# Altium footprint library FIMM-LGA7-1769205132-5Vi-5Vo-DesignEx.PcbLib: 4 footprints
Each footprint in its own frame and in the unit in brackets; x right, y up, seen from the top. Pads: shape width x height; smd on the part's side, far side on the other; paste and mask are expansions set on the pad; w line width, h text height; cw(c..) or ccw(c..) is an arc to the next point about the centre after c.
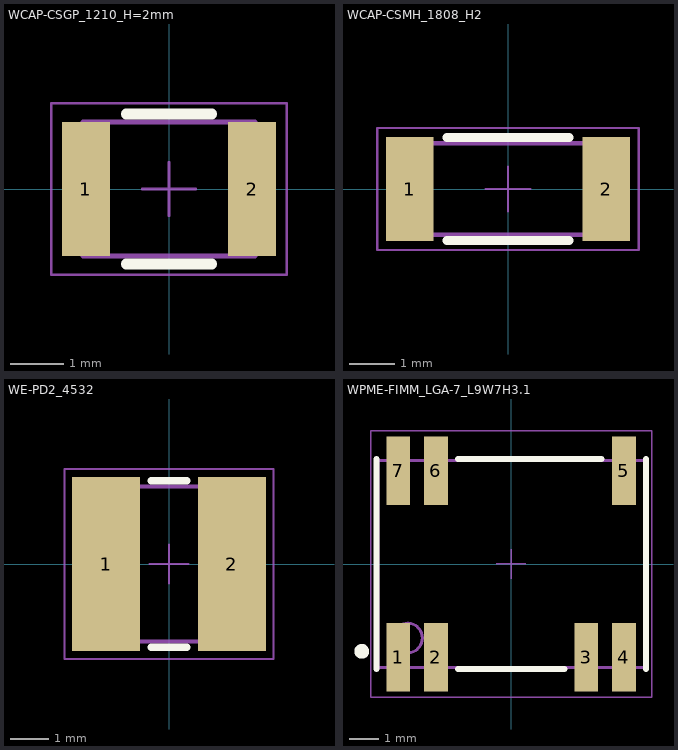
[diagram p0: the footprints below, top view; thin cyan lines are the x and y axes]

## WCAP-CSGP_1210_H=2mm [mm] "Ceramic Capacitors, body 3.2x2.5mm"
height 2.2
pads (2):
  rect 0.9x2.5 smd: 1(-1.55,0) 2(1.55,0)
Top Overlay:
  lines w0.2: -0.8,-1.4 0.8,-1.4 ; -0.8,1.4 0.8,1.4
Top Assembly:
  lines w0.1: -1.6,-1.25 1.6,-1.25 1.6,1.25 -1.6,1.25 -1.6,-1.25
  text ".Designator" at -1.4,-0.6 h1.2
Top 3D Body:
  lines w0.1: -1.6,-1.25 1.6,-1.25 1.6,1.25 -1.6,1.25 -1.6,-1.25
Top Courtyard:
  lines w0.05: -0.5,0 0.5,0 ; 0,-0.5 0,0.5 ; -2.2,-1.6 -2.2,1.6 2.2,1.6 2.2,-1.6 -2.2,-1.6
3D body "3.2x2.5x2x0.75.stp": height 2, standoff 0, extent -1.6,-1.25 1.6,1.25

## WCAP-CSMH_1808_H2 [mm] "Ceramic Capacitors, body 4.5x2.03mm"
height 2
pads (2):
  rect 1.05x2.3 smd: 1(-2.175,0) 2(2.175,0)
Top Overlay:
  lines w0.2: -1.35,-1.14 1.35,-1.14 ; -1.35,1.14 1.35,1.14
Top Assembly:
  lines w0.1: -2.25,-1.015 -2.25,1.015 2.25,1.015 2.25,-1.015 -2.25,-1.015
Top 3D Body:
  lines w0.1: -2.25,-1.015 2.25,-1.015 2.25,1.015 -2.25,1.015 -2.25,-1.015
Top Courtyard:
  lines w0.05: -0.5,0 0.5,0 ; 0,-0.5 0,0.5 ; -2.9,-1.35 -2.9,1.35 2.9,1.35 2.9,-1.35 -2.9,-1.35
3D body "4.5x2.03x2x0.5.stp": height 2, standoff 0, extent -2.25,-1.015 2.25,1.015

## WE-PD2_4532 [mm] "SMD Power Inductor, 2-Leads, body 4x4.5mm"
height 3.2
pads (2):
  rect 1.75x4.5 smd: 1(-1.625,0) 2(1.625,0)
Top Overlay:
  lines w0.2: -0.45,-2.15 0.45,-2.15 ; -0.45,2.15 0.45,2.15
Top Assembly:
  lines w0.1: -2.25,-2 -2.25,2 2.25,2 2.25,-2 -2.25,-2
Top 3D Body:
  lines w0.1: -2.25,-2 2.25,-2 2.25,2 -2.25,2 -2.25,-2
Top Courtyard:
  lines w0.05: -0.5,0 0.5,0 ; 0,-0.5 0,0.5 ; -2.7,-2.45 -2.7,2.45 2.7,2.45 2.7,-2.45 -2.7,-2.45
3D body "744773xxx.stp": height 3.22, standoff 0.02, extent -2.25,-2 2.25,2

## WPME-FIMM_LGA-7_L9W7H3.1 [mm] "Power Module, SMT, body 9.00x7.00mm"
height 3.2
pads (7):
  rect 0.8x2.3 smd: 1(-3.81,-3.15) 2(-2.54,-3.15) 3(2.54,-3.15) 4(3.81,-3.15) 5(3.81,3.15) 6(-2.54,3.15) 7(-3.81,3.15)
Top Overlay:
  circle w0.25: c-5.05,-2.95 r0.125
  lines w0.2: -4.55,-3.55 -4.55,3.55 ; -1.8,-3.55 1.8,-3.55 ; -1.8,3.55 3.05,3.55 ; 4.55,-3.55 4.55,3.55
Top Assembly:
  circle w0.1: c-3.5,-2.5 r0.5
  lines w0.1: -4.5,-3.5 -4.5,3.5 4.5,3.5 4.5,-3.5 -4.5,-3.5
  text ".Designator" at -7.498,-0.5 h1.5
Top 3D Body:
  circle w0.1: c-3.5,-2.5 r0.5
  lines w0.1: -4.5,-3.5 4.5,-3.5 4.5,3.5 -4.5,3.5 -4.5,-3.5
Top Courtyard:
  lines w0.05: -0.5,0 0.5,0 ; 0,-0.5 0,0.5 ; -4.75,-4.5 4.75,-4.5 4.75,4.5 -4.75,4.5 -4.75,-4.5
3D body "1769205132.stp": height 3.1, standoff 0, extent -4.5,-3.5 4.5,3.5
